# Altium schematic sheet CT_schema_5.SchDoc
size 250 x 245 mm
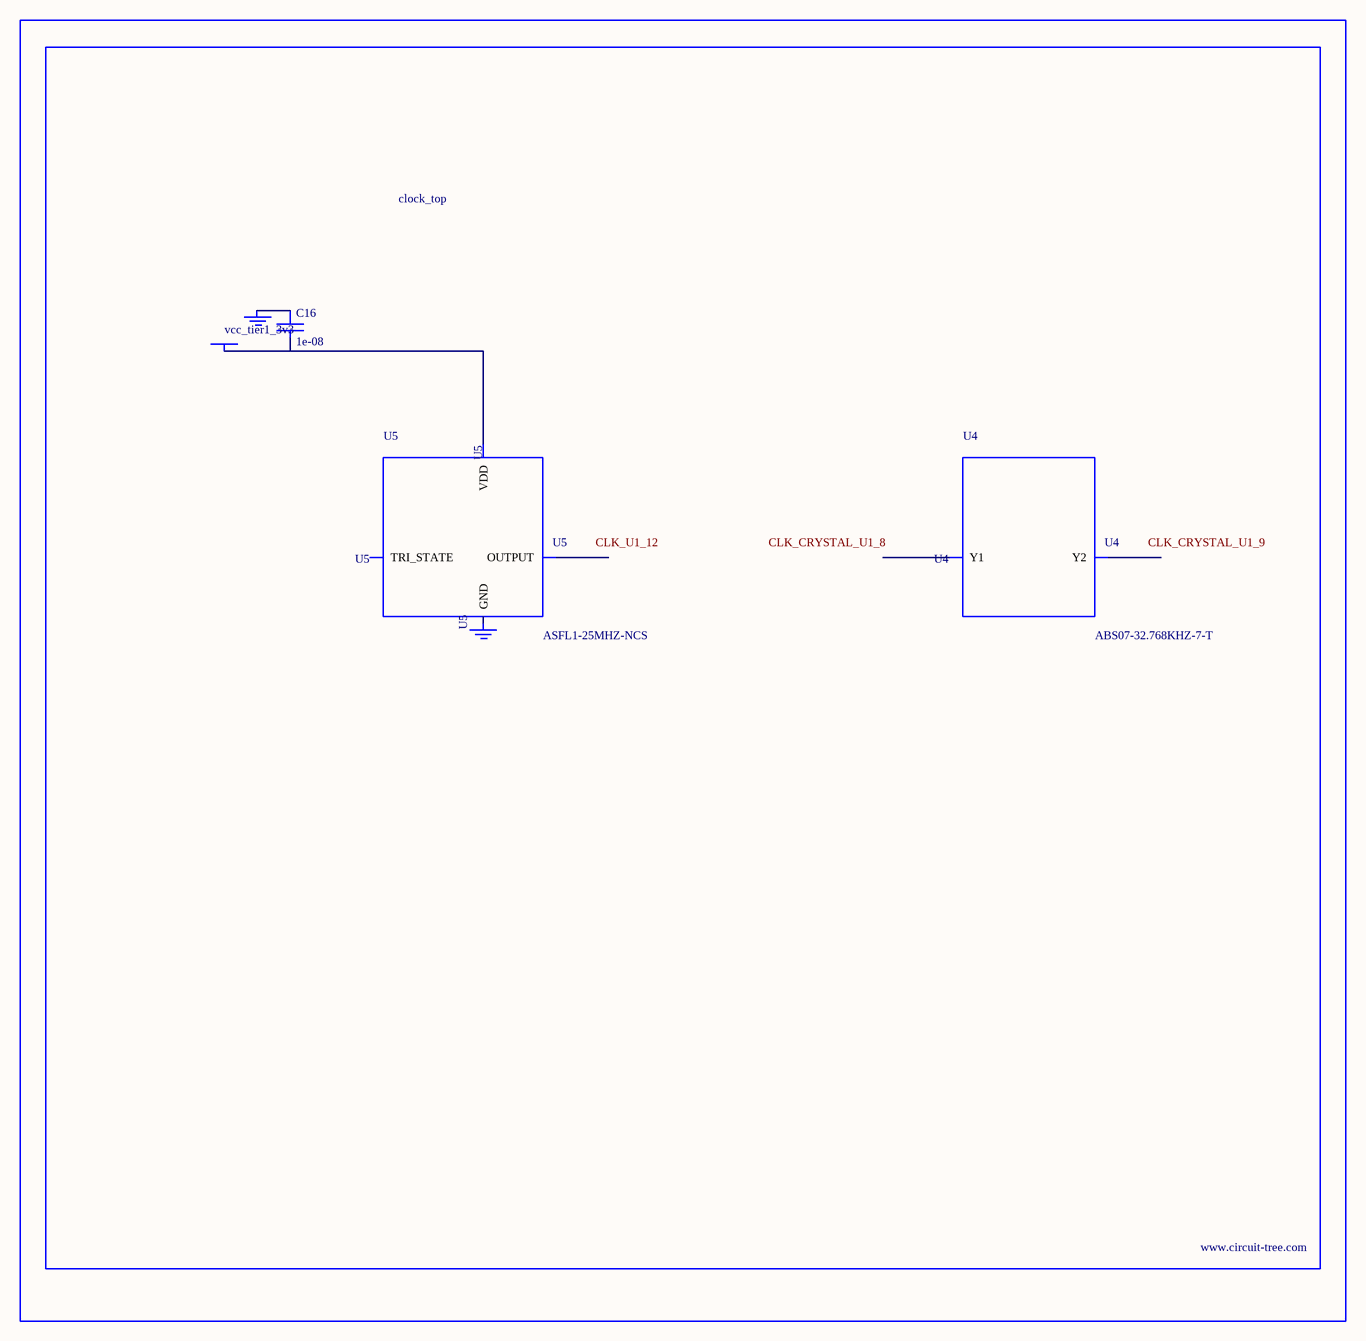
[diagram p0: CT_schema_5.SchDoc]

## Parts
BORDER4  (no value)
C16  1e-08  [C0402]
GND_INSTANCE_4_0  (no value)
GND_INSTANCE_4_1  (no value)
POWER_INSTANCE_4_0  vcc_tier1_3v3
U4  ABS07-32.768KHZ-7-T  [ABS07-32.768KHZ-7-T]
U5  ASFL1-25MHZ-NCS  [ASFL1]

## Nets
NetC16_1: C16.1 GND_INSTANCE_4_0.0(GND)
NetC16_2: C16.2 POWER_INSTANCE_4_0.0(PWR) U5.4(VDD)

Not connected (* = marked no-connect by the designer): GND_INSTANCE_4_1 0(GND); U4 1(Y1) 2(Y2); U5 1(TRI_STATE) 2(GND) 3(OUTPUT)

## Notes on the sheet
- Labels drawn without touching a wire or pin: CLK_CRYSTAL_U1_8, CLK_CRYSTAL_U1_9, CLK_U1_12

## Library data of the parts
BORDER4 = BORDER_PAGE4
C16 = C0402C103K3RAC
GND_INSTANCE_4_0 GND_INSTANCE_4_1 = GND
POWER_INSTANCE_4_0 = PWR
